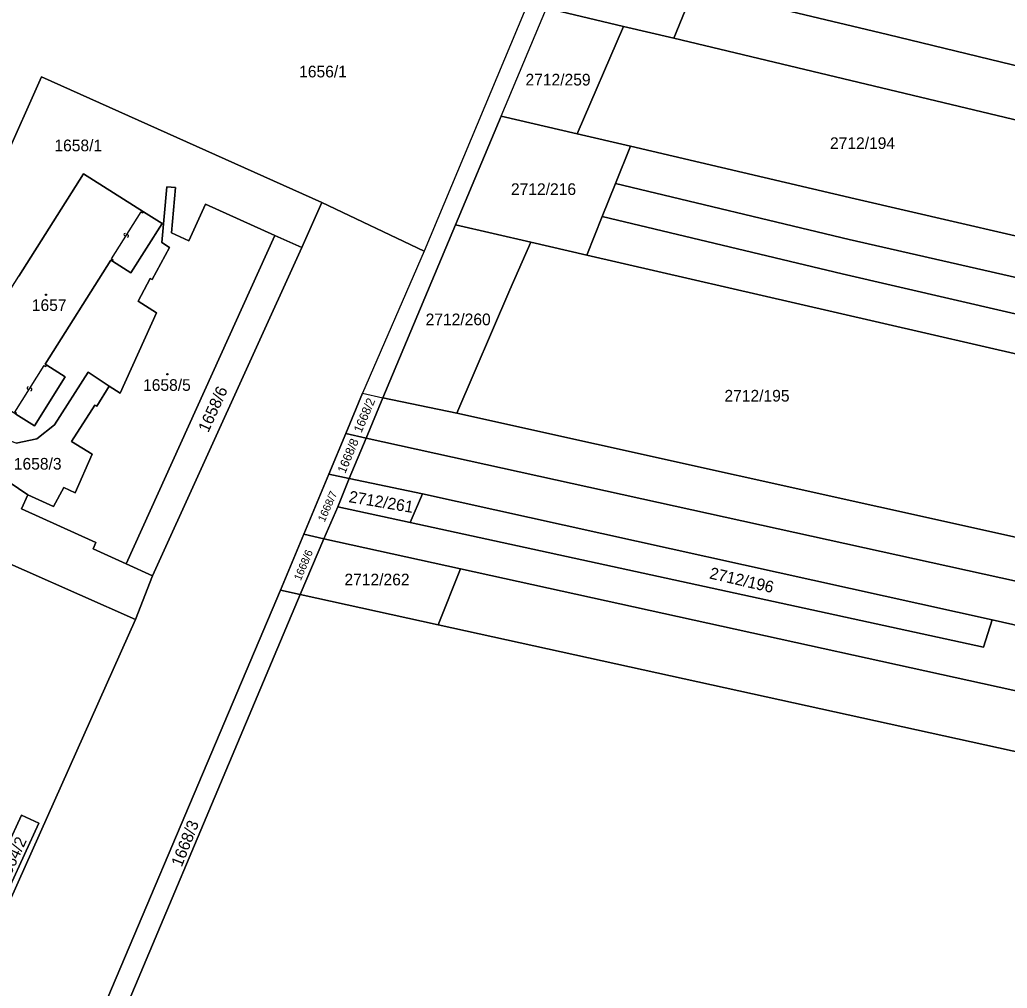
# Model space of a CAD drawing. Extents: x -596024 to -594475, y -1163820 to -1161957.
# Drawn here: x -595695.5 to -595551.7, y -1162246.5 to -1162105.4 of the extents above; entities that cross this region are included whole.
import ezdxf

# ---------------------------------------------------------------- set-up
doc = ezdxf.new("R2010")
doc.units = 0
for name, color, linetype in [('Level 1', 7, 'Continuous'), ('Level 13', 7, 'Continuous'), ('Level 3', 7, 'Continuous'), ('Level 4', 7, 'Continuous'), ('Level 5', 7, 'Continuous'), ('Level 60', 7, 'Continuous'), ('Vrstva 60', 7, 'Continuous')]:
    doc.layers.add(name, color=color, linetype=linetype)

msp = doc.modelspace()

# ---------------------------------------------------------------- linework, layer by layer
at = {"layer": 'Level 1'}
for points in [[(-595605.47, -1162064.69), (-595636.59, -1162139.13)], [(-595597.3, -1162100.8), (-595600.24, -1162108.12)], [(-595529.52, -1162117.18), (-595569.1, -1162107.57), (-595597.3, -1162100.8)], [(-595625.39, -1162119.44), (-595618.81, -1162103.71)], [(-595618.81, -1162103.71), (-595607.58, -1162106.39)], [(-595607.58, -1162106.39), (-595614.31, -1162122.04)], [(-595607.58, -1162106.39), (-595600.24, -1162108.12)], [(-595600.24, -1162108.12), (-595531.85, -1162124.44)], [(-595651.51, -1162132.01), (-595692.37, -1162113.74), (-595703.38, -1162138.38)], [(-595625.39, -1162119.44), (-595632.03, -1162135.3)], [(-595614.31, -1162122.04), (-595625.39, -1162119.44)], [(-595606.56, -1162123.84), (-595614.31, -1162122.04)], [(-595608.74, -1162129.27), (-595606.56, -1162123.84)], [(-595536.86, -1162140.03), (-595573.84, -1162131.52), (-595606.56, -1162123.84)], [(-595677.47, -1162133.37), (-595686.23, -1162127.88), (-595695.66, -1162142.76)], [(-595610.67, -1162134.07), (-595608.74, -1162129.27)], [(-595608.74, -1162129.27), (-595574.69, -1162137.44), (-595478.13, -1162159.4), (-595429.64, -1162170.28)], [(-595658.36, -1162136.86), (-595668.44, -1162132.29), (-595670.87, -1162137.6), (-595673.43, -1162136.43), (-595672.84, -1162129.86), (-595674.09, -1162129.76), (-595674.84, -1162137.84), (-595673.69, -1162138.58), (-595676.24, -1162143.25), (-595676.51, -1162143.08), (-595678.25, -1162146.41), (-595675.6, -1162148.12), (-595680.91, -1162159.82), (-595682.49, -1162158.77)], [(-595651.51, -1162132.01), (-595654.44, -1162138.6)], [(-595636.59, -1162139.13), (-595651.51, -1162132.01)], [(-595677.47, -1162133.37), (-595674.77, -1162135.07), (-595679.32, -1162142.28), (-595682.02, -1162140.58)], [(-595612.93, -1162139.69), (-595610.67, -1162134.07)], [(-595430.71, -1162175.3), (-595479.35, -1162164.7), (-595575.71, -1162142.44), (-595610.67, -1162134.07)], [(-595632.03, -1162135.3), (-595642.61, -1162160.49)], [(-595632.03, -1162135.3), (-595621.08, -1162137.82)], [(-595680.04, -1162184.66), (-595658.36, -1162136.86)], [(-595658.36, -1162136.86), (-595654.44, -1162138.6)], [(-595621.08, -1162137.82), (-595624.12, -1162144.77), (-595631.83, -1162162.74)], [(-595621.08, -1162137.82), (-595612.93, -1162139.69)], [(-595654.44, -1162138.6), (-595676.18, -1162186.39)], [(-595636.59, -1162139.13), (-595645.59, -1162159.83)], [(-595691.58, -1162155.73), (-595691.83, -1162155.57), (-595682.27, -1162140.42), (-595682.02, -1162140.58)], [(-595612.93, -1162139.69), (-595577.06, -1162147.96), (-595542.01, -1162156.02)], [(-595706, -1162144.24), (-595705.65, -1162145.68), (-595706.74, -1162150.45), (-595709, -1162156.03), (-595709.47, -1162159.02), (-595708.67, -1162162.88), (-595705.41, -1162167.16), (-595694.35, -1162174.62)], [(-595682.49, -1162158.77), (-595685.54, -1162156.73), (-595690.48, -1162164.41), (-595693.05, -1162166.47), (-595696.06, -1162167.08), (-595699.6, -1162165.82), (-595702.49, -1162163.98), (-595700.28, -1162160.29)], [(-595691.58, -1162155.73), (-595688.88, -1162157.43), (-595693.39, -1162164.58), (-595696.09, -1162162.88)], [(-595682.49, -1162158.77), (-595684.3, -1162161.7), (-595684.59, -1162161.53), (-595687.98, -1162166.87), (-595684.95, -1162168.68), (-595687.46, -1162174.33), (-595689.11, -1162173.55), (-595690.62, -1162176.3), (-595694.35, -1162174.62)], [(-595645.59, -1162159.83), (-595648.03, -1162165.69)], [(-595645.59, -1162159.83), (-595642.61, -1162160.49)], [(-595642.61, -1162160.49), (-595645.06, -1162166.35)], [(-595642.61, -1162160.49), (-595631.83, -1162162.74)], [(-595631.83, -1162162.74), (-595550.02, -1162180.9)], [(-595648.03, -1162165.69), (-595650.49, -1162171.59)], [(-595648.03, -1162165.69), (-595645.06, -1162166.35)], [(-595645.06, -1162166.35), (-595647.52, -1162172.25)], [(-595645.06, -1162166.35), (-595550.19, -1162187.23), (-595438.62, -1162211.79)], [(-595650.49, -1162171.59), (-595654.12, -1162180.36)], [(-595647.52, -1162172.25), (-595650.49, -1162171.59)], [(-595649.18, -1162176.36), (-595647.52, -1162172.25)], [(-595636.87, -1162174.47), (-595647.52, -1162172.25)], [(-595719.62, -1162174.71), (-595711.16, -1162178.38), (-595678.68, -1162192.78)], [(-595694.35, -1162174.62), (-595695.27, -1162176.64), (-595684.44, -1162181.57), (-595684.84, -1162182.49), (-595680.04, -1162184.66)], [(-595636.87, -1162174.47), (-595638.64, -1162178.65)], [(-595553.86, -1162192.84), (-595636.87, -1162174.47)], [(-595651.23, -1162181), (-595649.18, -1162176.36)], [(-595649.18, -1162176.36), (-595638.64, -1162178.65)], [(-595638.64, -1162178.65), (-595555.14, -1162196.79), (-595553.86, -1162192.84)], [(-595654.12, -1162180.36), (-595657.55, -1162188.49)], [(-595654.65, -1162189.13), (-595651.23, -1162181)], [(-595654.12, -1162180.36), (-595651.23, -1162181)], [(-595651.23, -1162181), (-595631.3, -1162185.38)], [(-595676.18, -1162186.39), (-595680.04, -1162184.66)], [(-595634.58, -1162193.53), (-595631.3, -1162185.38)], [(-595631.3, -1162185.38), (-595521.27, -1162209.58), (-595441.71, -1162226.71)], [(-595676.18, -1162186.39), (-595678.68, -1162192.78)], [(-595657.55, -1162188.49), (-595692.14, -1162270.15)], [(-595654.65, -1162189.13), (-595657.55, -1162188.49)], [(-595689.12, -1162270.78), (-595654.65, -1162189.13)], [(-595634.58, -1162193.53), (-595654.65, -1162189.13)], [(-595678.68, -1162192.78), (-595709.83, -1162262.45)], [(-595634.58, -1162193.53), (-595523.1, -1162218.01), (-595443.87, -1162235.17)], [(-595439.88, -1162217.66), (-595519.7, -1162200.54), (-595553.86, -1162192.84)], [(-595699.06, -1162236.11), (-595701.56, -1162234.96), (-595695.28, -1162221.28), (-595692.76, -1162222.44), (-595699.06, -1162236.11)]]:
    msp.add_lwpolyline(points, dxfattribs=at)
at = {"layer": 'Level 13'}
for centre, start, end in [((-595680.16, -1162136.72), 95.0908, 327.1888), ((-595679.84, -1162136.92), 274.8764, 147.4664), ((-595694.26, -1162159.06), 95.0876, 327.1856), ((-595693.94, -1162159.26), 274.8731, 147.4631)]:
    msp.add_arc(centre, 0.184, start, end, dxfattribs=at)
at = {"layer": 'Level 3'}
for points in [[(-595682.02, -1162140.58), (-595681.91, -1162140.41), (-595682.17, -1162140.25), (-595677.83, -1162133.38), (-595677.58, -1162133.54), (-595677.47, -1162133.37)], [(-595696.09, -1162162.88), (-595695.98, -1162162.71), (-595696.24, -1162162.55), (-595691.95, -1162155.76), (-595691.7, -1162155.92), (-595691.58, -1162155.73)]]:
    msp.add_lwpolyline(points, dxfattribs=at)
at = {"layer": 'Level 5'}
for centre, radius in [((-595691.69, -1162145.47), 0.09), ((-595691.69, -1162145.47), 0.0521), ((-595674.02, -1162157.05), 0.09), ((-595674.02, -1162157.05), 0.0521)]:
    msp.add_circle(centre, radius, dxfattribs=at)
at = {"layer": 'Level 60'}
for points in [[(-595698.23, -1162081.48), (-595688.29, -1162059.74), (-595687.27, -1162058.23), (-595685.95, -1162057.58), (-595683.76, -1162058.04), (-595673.56, -1162062.13), (-595669.16, -1162051.9), (-595666.53, -1162053.03), (-595651.98, -1162059.14), (-595650.49, -1162054.85), (-595667.27, -1162047.5), (-595664.46, -1162040.96), (-595663.57, -1162041.38), (-595662.76, -1162040.03), (-595661.92, -1162040.41), (-595661.68, -1162039.89), (-595653.01, -1162043.65), (-595648.38, -1162045.78), (-595646.62, -1162046.56), (-595605.47, -1162064.69), (-595636.59, -1162139.13), (-595651.51, -1162132.01), (-595692.37, -1162113.74), (-595703.38, -1162138.38)], [(-595703.38, -1162138.38), (-595692.37, -1162113.74), (-595651.51, -1162132.01), (-595654.44, -1162138.6), (-595658.36, -1162136.86), (-595668.44, -1162132.29), (-595670.87, -1162137.6), (-595673.43, -1162136.43), (-595672.84, -1162129.86), (-595674.09, -1162129.76), (-595674.84, -1162137.84), (-595673.69, -1162138.58), (-595676.24, -1162143.25), (-595676.51, -1162143.08), (-595678.25, -1162146.41), (-595675.6, -1162148.12), (-595680.91, -1162159.82), (-595682.49, -1162158.77), (-595685.54, -1162156.73), (-595690.48, -1162164.41), (-595693.05, -1162166.47), (-595696.06, -1162167.08)], [(-595696.09, -1162162.88), (-595693.39, -1162164.58), (-595688.88, -1162157.43), (-595691.58, -1162155.73), (-595691.83, -1162155.57), (-595682.27, -1162140.42), (-595682.02, -1162140.58), (-595679.32, -1162142.28), (-595674.77, -1162135.07), (-595677.47, -1162133.37), (-595686.23, -1162127.88), (-595695.66, -1162142.76)], [(-595709.83, -1162262.45), (-595678.68, -1162192.78), (-595676.18, -1162186.39), (-595654.44, -1162138.6), (-595651.51, -1162132.01), (-595636.59, -1162139.13), (-595645.59, -1162159.83), (-595648.03, -1162165.69), (-595650.49, -1162171.59), (-595654.12, -1162180.36), (-595657.55, -1162188.49), (-595692.14, -1162270.15), (-595695.06, -1162277.29), (-595697.99, -1162284.45)], [(-595696.06, -1162167.08), (-595693.05, -1162166.47), (-595690.48, -1162164.41), (-595685.54, -1162156.73), (-595682.49, -1162158.77), (-595684.3, -1162161.7), (-595684.59, -1162161.53), (-595687.98, -1162166.87), (-595684.95, -1162168.68), (-595687.46, -1162174.33), (-595689.11, -1162173.55), (-595690.62, -1162176.3), (-595694.35, -1162174.62), (-595705.41, -1162167.16)]]:
    msp.add_lwpolyline(points, dxfattribs=at)
for points in [[(-595519.9, -1162056.48), (-595510.72, -1162058.81), (-595529.52, -1162117.18), (-595569.1, -1162107.57), (-595597.3, -1162100.8), (-595604.46, -1162099.1), (-595582.47, -1162047.97), (-595579.93, -1162041.11), (-595573.87, -1162042.66)], [(-595604.46, -1162099.1), (-595597.3, -1162100.8), (-595600.24, -1162108.12), (-595607.58, -1162106.39), (-595618.81, -1162103.71), (-595615.75, -1162096.4)], [(-595423.19, -1162142.18), (-595424.9, -1162149.3), (-595473.29, -1162138.61), (-595531.85, -1162124.44), (-595600.24, -1162108.12), (-595597.3, -1162100.8), (-595569.1, -1162107.57), (-595529.52, -1162117.18), (-595471.58, -1162131.45)], [(-595618.81, -1162103.71), (-595607.58, -1162106.39), (-595614.31, -1162122.04), (-595625.39, -1162119.44)], [(-595607.58, -1162106.39), (-595600.24, -1162108.12), (-595531.85, -1162124.44), (-595536.86, -1162140.03), (-595573.84, -1162131.52), (-595606.56, -1162123.84), (-595614.31, -1162122.04)], [(-595614.31, -1162122.04), (-595606.56, -1162123.84), (-595608.74, -1162129.27), (-595610.67, -1162134.07), (-595612.93, -1162139.69), (-595621.08, -1162137.82), (-595632.03, -1162135.3), (-595625.39, -1162119.44)], [(-595573.84, -1162131.52), (-595536.86, -1162140.03), (-595477.03, -1162154.15), (-595428.5, -1162164.95), (-595429.64, -1162170.28), (-595478.13, -1162159.4), (-595574.69, -1162137.44), (-595608.74, -1162129.27), (-595606.56, -1162123.84)], [(-595686.23, -1162127.88), (-595677.47, -1162133.37), (-595674.77, -1162135.07), (-595679.32, -1162142.28), (-595682.02, -1162140.58), (-595682.27, -1162140.42), (-595691.83, -1162155.57), (-595691.58, -1162155.73), (-595688.88, -1162157.43), (-595693.39, -1162164.58), (-595696.09, -1162162.88), (-595700.28, -1162160.29), (-595701.37, -1162159.6), (-595704.88, -1162157.34), (-595696.84, -1162144.63), (-595695.66, -1162142.76)], [(-595610.67, -1162134.07), (-595608.74, -1162129.27), (-595574.69, -1162137.44), (-595478.13, -1162159.4), (-595429.64, -1162170.28), (-595430.71, -1162175.3), (-595479.35, -1162164.7), (-595575.71, -1162142.44)], [(-595668.44, -1162132.29), (-595658.36, -1162136.86), (-595680.04, -1162184.66), (-595684.84, -1162182.49), (-595684.44, -1162181.57), (-595695.27, -1162176.64), (-595694.35, -1162174.62), (-595690.62, -1162176.3), (-595689.11, -1162173.55), (-595687.46, -1162174.33), (-595684.95, -1162168.68), (-595687.98, -1162166.87), (-595684.59, -1162161.53), (-595684.3, -1162161.7), (-595682.49, -1162158.77), (-595680.91, -1162159.82), (-595675.6, -1162148.12), (-595678.25, -1162146.41), (-595676.51, -1162143.08), (-595676.24, -1162143.25), (-595673.69, -1162138.58), (-595674.84, -1162137.84), (-595674.09, -1162129.76), (-595672.84, -1162129.86), (-595673.43, -1162136.43), (-595670.87, -1162137.6)], [(-595577.06, -1162147.96), (-595612.93, -1162139.69), (-595610.67, -1162134.07), (-595575.71, -1162142.44), (-595479.35, -1162164.7), (-595430.71, -1162175.3), (-595431.88, -1162180.75), (-595481.06, -1162170.15), (-595542.01, -1162156.02)], [(-595642.61, -1162160.49), (-595632.03, -1162135.3), (-595621.08, -1162137.82), (-595624.12, -1162144.77), (-595631.83, -1162162.74)], [(-595654.44, -1162138.6), (-595676.18, -1162186.39), (-595680.04, -1162184.66), (-595658.36, -1162136.86)], [(-595612.93, -1162139.69), (-595577.06, -1162147.96), (-595542.01, -1162156.02), (-595550.02, -1162180.9), (-595631.83, -1162162.74), (-595624.12, -1162144.77), (-595621.08, -1162137.82)], [(-595676.18, -1162186.39), (-595678.68, -1162192.78), (-595711.16, -1162178.38), (-595719.62, -1162174.71), (-595706, -1162144.24), (-595705.65, -1162145.68), (-595706.74, -1162150.45), (-595709, -1162156.03), (-595709.47, -1162159.02), (-595708.67, -1162162.88), (-595705.41, -1162167.16), (-595694.35, -1162174.62), (-595695.27, -1162176.64), (-595684.44, -1162181.57), (-595684.84, -1162182.49), (-595680.04, -1162184.66)], [(-595645.59, -1162159.83), (-595642.61, -1162160.49), (-595645.06, -1162166.35), (-595648.03, -1162165.69)], [(-595516.52, -1162188.48), (-595437.24, -1162205.32), (-595438.62, -1162211.79), (-595550.19, -1162187.23), (-595645.06, -1162166.35), (-595642.61, -1162160.49), (-595631.83, -1162162.74), (-595550.02, -1162180.9)], [(-595648.03, -1162165.69), (-595645.06, -1162166.35), (-595647.52, -1162172.25), (-595650.49, -1162171.59)], [(-595645.06, -1162166.35), (-595550.19, -1162187.23), (-595438.62, -1162211.79), (-595439.88, -1162217.66), (-595519.7, -1162200.54), (-595553.86, -1162192.84), (-595636.87, -1162174.47), (-595647.52, -1162172.25)], [(-595649.18, -1162176.36), (-595651.23, -1162181), (-595654.12, -1162180.36), (-595650.49, -1162171.59), (-595647.52, -1162172.25)], [(-595649.18, -1162176.36), (-595647.52, -1162172.25), (-595636.87, -1162174.47), (-595638.64, -1162178.65)], [(-595737.72, -1162230.18), (-595737.2, -1162230.4), (-595736.68, -1162229.18), (-595736.59, -1162229.22), (-595722.85, -1162197.97), (-595728.5, -1162195.42), (-595727.18, -1162192.39), (-595727.53, -1162192.23), (-595719.62, -1162174.71), (-595711.16, -1162178.38), (-595678.68, -1162192.78), (-595709.83, -1162262.45), (-595734.57, -1162251.78), (-595745.21, -1162247.19)], [(-595555.14, -1162196.79), (-595638.64, -1162178.65), (-595636.87, -1162174.47), (-595553.86, -1162192.84)], [(-595439.88, -1162217.66), (-595441.71, -1162226.71), (-595521.27, -1162209.58), (-595631.3, -1162185.38), (-595651.23, -1162181), (-595649.18, -1162176.36), (-595638.64, -1162178.65), (-595555.14, -1162196.79), (-595553.86, -1162192.84), (-595519.7, -1162200.54)], [(-595651.23, -1162181), (-595654.65, -1162189.13), (-595657.55, -1162188.49), (-595654.12, -1162180.36)], [(-595654.65, -1162189.13), (-595651.23, -1162181), (-595631.3, -1162185.38), (-595634.58, -1162193.53)], [(-595441.71, -1162226.71), (-595442.1, -1162228.6), (-595443.87, -1162235.17), (-595523.1, -1162218.01), (-595634.58, -1162193.53), (-595631.3, -1162185.38), (-595521.27, -1162209.58)], [(-595689.12, -1162270.78), (-595692.14, -1162270.15), (-595657.55, -1162188.49), (-595654.65, -1162189.13)], [(-595631.74, -1162282.65), (-595689.12, -1162270.78), (-595654.65, -1162189.13), (-595634.58, -1162193.53), (-595523.1, -1162218.01), (-595443.87, -1162235.17), (-595465.88, -1162317.29), (-595541.86, -1162301.58)], [(-595701.56, -1162234.96), (-595699.06, -1162236.11), (-595692.76, -1162222.44), (-595695.28, -1162221.28)], [(-595699.06, -1162236.11), (-595701.56, -1162234.96), (-595695.28, -1162221.28), (-595692.76, -1162222.44)]]:
    msp.add_lwpolyline(points, close=True, dxfattribs=at)
at = {"layer": 'Vrstva 60'}
msp.add_lwpolyline([(-595558.7, -1161956.88), (-595561.96, -1161956.88), (-595572.78, -1161984.7), (-595605.47, -1162064.69), (-595636.59, -1162139.13), (-595645.59, -1162159.83), (-595642.61, -1162160.49), (-595632.03, -1162135.3), (-595625.39, -1162119.44), (-595618.81, -1162103.71), (-595615.75, -1162096.4), (-595602.7, -1162066), (-595591.42, -1162038.27), (-595580.65, -1162012.51), (-595563.95, -1161970.42), (-595560.71, -1161962.17)], close=True, dxfattribs=at)

# ---------------------------------------------------------------- texts
at = {"layer": 'Level 4'}
for s, p in [('1656/1', (-595654.82, -1162113.81)), ('2712/259', (-595621.85, -1162114.99)), ('1658/1', (-595690.47, -1162124.57)), ('2712/194', (-595577.5, -1162124.24)), ('2712/216', (-595623.97, -1162130.94)), ('1657', (-595693.76, -1162147.83)), ('2712/260', (-595636.4, -1162149.91)), ('1658/5', (-595677.56, -1162159.47)), ('2712/195', (-595592.87, -1162161.03)), ('1658/3', (-595696.38, -1162170.94)), ('2712/262', (-595648.22, -1162187.8))]:
    msp.add_text(s, height=1.7, dxfattribs=at).set_placement(p)
for s, height, rotation, p in [('1658/6', 1.7, 65.5389, (-595668.06, -1162165.64)), ('1668/2', 1.28, 66.8041, (-595645.76, -1162165.68)), ('1668/8', 1.28, 67.4513, (-595648.11, -1162171.59)), ('1668/7', 1.14, 66.1637, (-595651.12, -1162178.66)), ('2712/261', 1.7, 350.3624, (-595647.68, -1162175.67)), ('1668/6', 1.14, 67.1853, (-595654.59, -1162187.21)), ('2712/196', 1.7, 346.9377, (-595595.16, -1162186.78)), ('1668/3', 1.7, 68.4496, (-595671.93, -1162228.92)), ('1664/2', 1.7, 65.3418, (-595697.35, -1162231.25))]:
    msp.add_text(s, height=height, rotation=rotation, dxfattribs=at).set_placement(p)

doc.saveas('drawing.dxf')
